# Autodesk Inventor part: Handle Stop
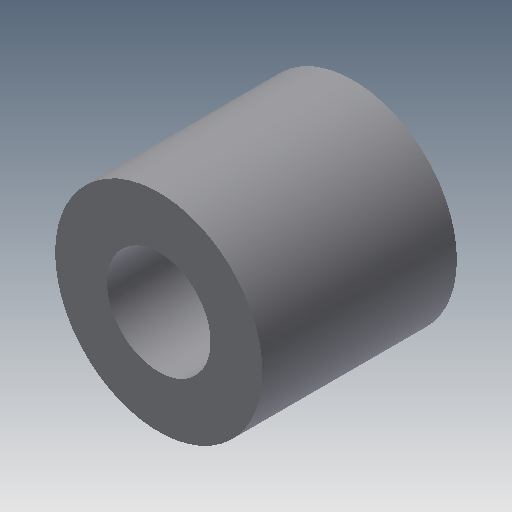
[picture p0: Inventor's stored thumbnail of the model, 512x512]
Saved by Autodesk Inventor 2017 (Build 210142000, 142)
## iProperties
Shininess: 77.0
Length Units: 11269
Angle Units: 11279
Time Units: 11290
Mass Units: 11283
Length Display Precision: 3
Angle Display Precision: 2
Compacted: True
Created: 2002-02
Part Number: Handle Stop
Document SubType Name: Modeling
Designer: ***
Density: 1 g/cm^3
Material: Generic
Mass: 2.36248 g
Surface Area: 14.8283 cm^2
Volume: 2.36248 cm^3
Appearance: Default
Density: 0.0
Volumn: 0.0
Area: 0.0
PropertySet Name: Model Information
Control State: 0
Master: False
Checked Out: False
Author: ***
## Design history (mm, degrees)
sketch "Sketch1"
  geometry: L1 (0, 0)-(0, -2); L2 (0, -2)-(8, -2); L3 (8, -2)-(8, 13); L4 (8, 13)-(4, 13); L5 (4, 13)-(4, 0); L6 (4, 0)-(0, 0)
  constraints: 12 end point, 4 parallel, 1 perpendicular, 1 vertical
  dimensions: "d0" = 16 diameter of L3 L1; "d1" = 8 diameter of L5 L1; "d2" = 2 distance of L1.start L1.end; "d3" = 15 distance of L2.end L3.end
revolve "Revolution1" sketch "Sketch1" stored, may be unused: angle "d4" = 90 deg
body "Solid1"
